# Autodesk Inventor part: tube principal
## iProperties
Shininess: 70.0
Length Units: 11269
Angle Units: 11279
Time Units: 11290
Mass Units: 11283
Length Display Precision: 3
Angle Display Precision: 2
Created: 2002-06
Part Number: tube principal
Material: Par défaut
Document SubType Name: Modélisation
Designer: REVEST Pierre
Density: 0.0
Volumn: 0.0
Area: 0.0
PropertySet Name: Model Information
Control State: 0
Master: False
Checked Out: False
Author: REVEST Pierre
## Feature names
1. Extrusion1
2. Perçage1 [Hole]
3. Perçage2 [Hole]
4. Perçage3 [Hole]
5. Perçage4 [Hole]
6. Extrusion2
7. Extrusion3
8. Congé1 [Fillet]
9. Congé2 [Fillet]
10. Réseau circulaire1 [Circular Pattern]
11. Extrusion5
